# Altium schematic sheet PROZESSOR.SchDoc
size A3; PageSetup: Record=PageOptions|CenterHorizontal=True|CenterVertical=True|PrintScale=0.70|XCorrection=1.00|YCorrection=1.00|PrintKind=0|BorderSize=5000000|LeftOffset=5|BottomOffset=0|Orientation=1|PaperLength=1000|PaperWidth=1000|Scale=100|PaperSource=7|PrintQuality=-4|MediaType=1|DitherType=10|PaperKind=A4|PrintScaleMode=1
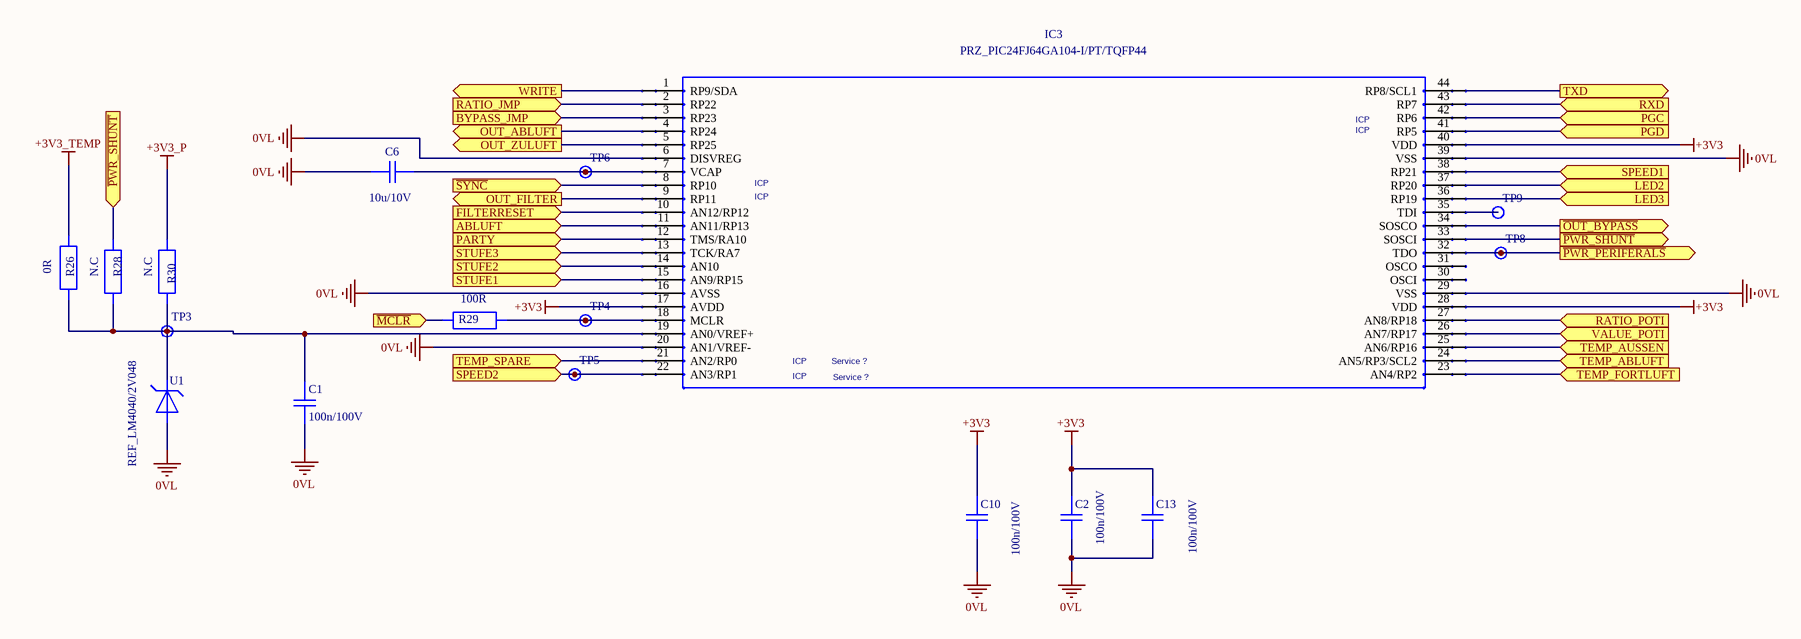
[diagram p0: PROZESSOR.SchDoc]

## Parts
C1  value 100n/100V  (hidden comment: C12/100N)
C2  value 100n/100V  (hidden comment: C12/100N)
C6  value 10u/10V  (hidden comment: C12/10U/10V/X7R)
C10  value 100n/100V  (hidden comment: C12/100N)
C13  value 100n/100V  (hidden comment: C12/100N)
IC3  PRZ_PIC24FJ64GA104-I/PT/TQFP44
R26  value 0R  (hidden comment: R12/0R)
R28  value N.C  (hidden comment: R12/NC)
R29  value 100R  (hidden comment: R12/100R)
R30  value N.C  (hidden comment: R12/NC)
TP3  LP10  (value not drawn)  (no BOM)
TP4  LP10  (value not drawn)  (no BOM)
TP5  LP10  (value not drawn)  (no BOM)
TP6  LP10  (value not drawn)  (no BOM)
TP8  LP10  (value not drawn)  (no BOM)
TP9  LP10  (value not drawn)  (no BOM)
U1  REF_LM4040/2V048

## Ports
ABLUFT, BYPASS_JMP, FILTERRESET, LED2, LED3, OUT_ABLUFT, OUT_FILTER, OUT_ZULUFT, PARTY, PGC, PGD, RATIO_JMP, RATIO_POTI, RXD, SPEED1, SPEED2, STUFE1, STUFE2, STUFE3, TEMP_ABLUFT, TEMP_AUSSEN, TEMP_FORTLUFT, TEMP_SPARE, TXD, VALUE_POTI, WRITE, ~{MCLR}, ~{OUT_BYPASS}, ~{PWR_PERIFERALS}, ~{PWR_SHUNT}, ~{SYNC}

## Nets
0VL: C1.1 C2.1 C6.2 C10.1 C13.1 IC3.6(DISVREG) IC3.16(AVSS) IC3.20(AN1/VREF-) IC3.29(VSS) IC3.39(VSS) U1.2
+3V3: C2.2 C10.2 C13.2 IC3.17(AVDD) IC3.28(VDD) IC3.40(VDD)
+3V3_P: R30.2
+3V3_TEMP: R26.2
~{MCLR}: R29.2 ; port ~{MCLR}
~{OUT_BYPASS}: IC3.34(SOSCO) ; port ~{OUT_BYPASS}
~{PWR_PERIFERALS}: IC3.32(TDO) TP8.1 ; port ~{PWR_PERIFERALS}
~{PWR_SHUNT}: IC3.33(SOSCI) R28.2 ; port ~{PWR_SHUNT}
~{SYNC}: IC3.8(RP10) ; port ~{SYNC}
ABLUFT: IC3.11(AN11/RP13) ; port ABLUFT
BYPASS_JMP: IC3.3(RP23) ; port BYPASS_JMP
FILTERRESET: IC3.10(AN12/RP12) ; port FILTERRESET
LED2: IC3.37(RP20) ; port LED2
LED3: IC3.36(RP19) ; port LED3
OUT_ABLUFT: IC3.4(RP24) ; port OUT_ABLUFT
OUT_FILTER: IC3.9(RP11) ; port OUT_FILTER
OUT_ZULUFT: IC3.5(RP25) ; port OUT_ZULUFT
PARTY: IC3.12(TMS/RA10) ; port PARTY
PGC: IC3.42(RP6) ; port PGC
PGD: IC3.41(RP5) ; port PGD
RATIO_JMP: IC3.2(RP22) ; port RATIO_JMP
RATIO_POTI: IC3.27(AN8/RP18) ; port RATIO_POTI
RXD: IC3.43(RP7) ; port RXD
SPEED1: IC3.38(RP21) ; port SPEED1
SPEED2: IC3.22(AN3/RP1) TP5.1 ; port SPEED2
STUFE1: IC3.15(AN9/RP15) ; port STUFE1
STUFE2: IC3.14(AN10) ; port STUFE2
STUFE3: IC3.13(TCK/RA7) ; port STUFE3
TEMP_ABLUFT: IC3.24(AN5/RP3/SCL2) ; port TEMP_ABLUFT
TEMP_AUSSEN: IC3.25(AN6/RP16) ; port TEMP_AUSSEN
TEMP_FORTLUFT: IC3.23(AN4/RP2) ; port TEMP_FORTLUFT
TEMP_SPARE: IC3.21(AN2/RP0) ; port TEMP_SPARE
TXD: IC3.44(RP8/SCL1) ; port TXD
VALUE_POTI: IC3.26(AN7/RP17) ; port VALUE_POTI
WRITE: IC3.1(RP9/SDA) ; port WRITE
NetC1_2: C1.2 IC3.19(AN0/VREF+) R26.1 R28.1 R30.1 TP3.1 U1.1
NetC6_1: C6.1 IC3.7(VCAP) TP6.1
NetIC3_18: IC3.18(MCLR) R29.1 TP4.1
NetIC3_35: IC3.35(TDI) TP9.1

Not connected (* = marked no-connect by the designer): IC3 30(OSCI) 31(OSCO)

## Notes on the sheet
- (near IC3) ICP
- (near IC3) Service ?

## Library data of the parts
C1 C2 C10 C13 = C12/100N: PART DESCE: CHIP-CAP. CERAMIC 0.10UF 100V X7R 10% 1206; SUPP.ART.#2: 399-1805-1-ND; SUPP.#2: DIGIKEY; SUPP.ART.#1: 52 D 975; SUPP.#1: BUERKLIN; TYPE.#2: C1206C104K1RACTU; GR: C; MFG.#1: EPCOS; TYPE: B37872K1104K062; Geometry.Height: 0.99mm; PCB DECAL: R02X125Y0A0
C6 = C12/10U/10V/X7R: PART DESCE: CHIP-CAP. 10u  X7R  10V 10%; Geometry.Height: 0.99mm; TYPE: C1206C106K8RACTU; MFG.#1: KEMET; GR: C7; SUPP.#1: DIGIKEY; SUPP.ART.#1: 399-4937-6-ND; PCB DECAL: C02X125Y0A0
IC3 = PRZ_PIC24FJ64GA104-I/PT/TQFP44: PART DESCE: MICROPROZESSOR; PCB DECAL: UF44X313Y313A0; Geometry.Height: 0.99060mm; SUPP.ART.#1: 1778482; SUPP.#1: FARNELL; MFG.#1: MICROCHIP
R26 = R12/0R: PART DESCE: MINI-MELF 1% 1/4W; Geometry.Height: 3.20040mm; MFG.#1: BEYSCHLAG; GR: R; SUPP.#1: BUERKLIN; SUPP.ART.#1: 06 E 500; PCB DECAL: R02X125Y0A0
R28 R30 = R12/NC: PART DESCE: MINI-MELF 1% 1/4W; Geometry.Height: 126; MFG.#1: BEYSCHLAG; GR: R; PCB DECAL: R02X125Y0A0
R29 = R12/100R: PART DESCE: MINI-MELF 1% 1/4W or 1206; Geometry.Height: 3.20040mm; MFG.#1: BEYSCHLAG; GR: R3; SUPP.#1: BUERKLIN; SUPP.ART.#1: 06 E 568; PCB DECAL: R02X125Y0A0
TP3-TP6 TP8 TP9 = LP10: PART DESCE: SOLDER PIN 0,9 mm; MFG.#1: ETTINGER; GR: TP; SUPP.#1: BUERKLIN; SUPP.ART.#1: 12 H 6158; PCB DECAL: TP01X0Y0B39
U1 = REF_LM4040/2V048: PART DESCE: NC; VALUE: NC; GR: UR; Geometry.Height: 1.12mm; PCB DECAL: TR03X80Y95A0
